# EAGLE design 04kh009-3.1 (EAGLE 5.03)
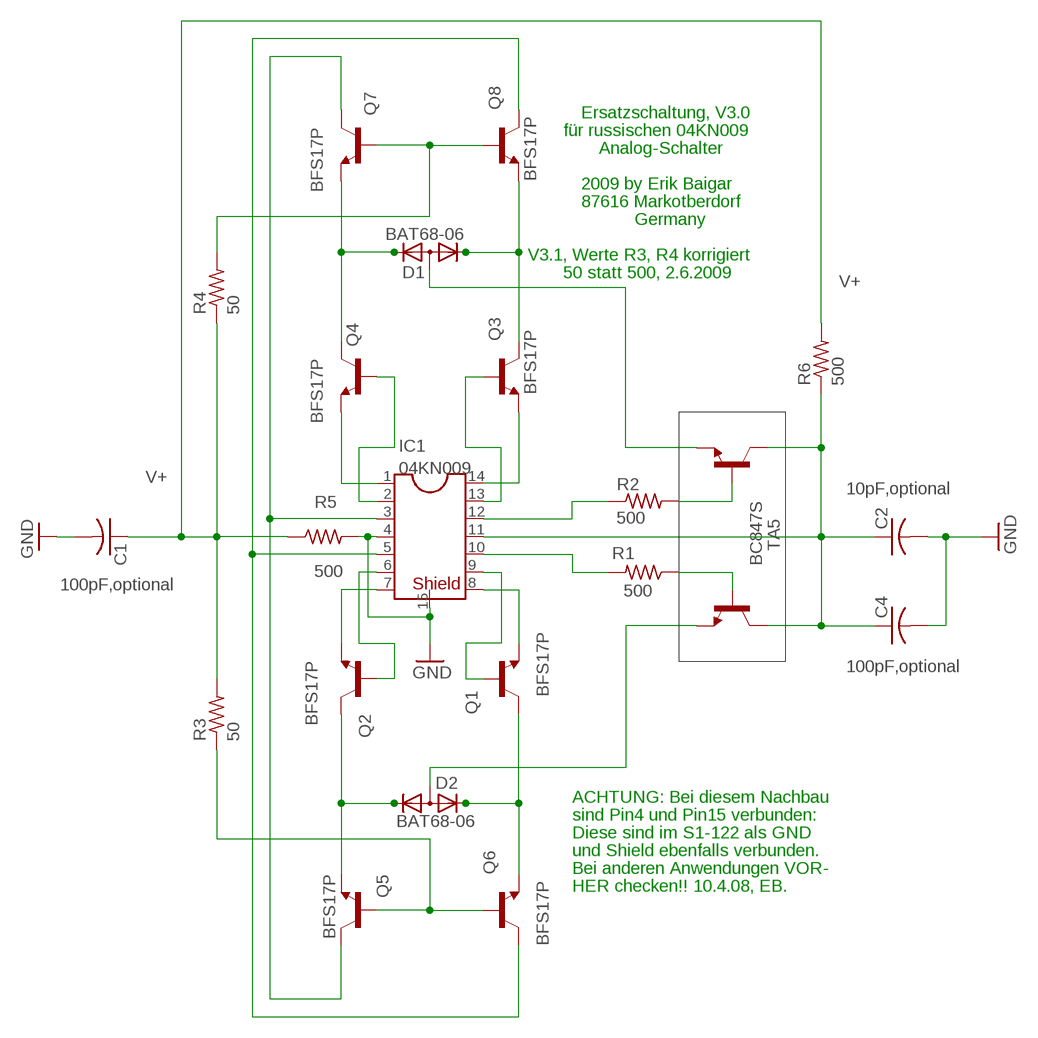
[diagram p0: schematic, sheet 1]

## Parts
C1  100pF,optional  C-USC0805  [C0805]
C2  10pF,optional  C-USC0805  [C0805]
C4  100pF,optional  C-USC0805  [C0805]
D1  BAT68-06  [SOT23]
D2  BAT68-06  [SOT23]
IC1  04KN009  04KH009  [04KH009]
Q1  BFS17P  BC847ASMD  [SOT23]
Q2  BFS17P  BC847ASMD  [SOT23]
Q3  BFS17P  BC847ASMD  [SOT23]
Q4  BFS17P  BC847ASMD  [SOT23]
Q5  BFS17P  BC847ASMD  [SOT23]
Q6  BFS17P  BC847ASMD  [SOT23]
Q7  BFS17P  BC847ASMD  [SOT23]
Q8  BFS17P  BC847ASMD  [SOT23]
R1  500  R-US_R0603  [R0603]
R2  500  R-US_R0603  [R0603]
R3  50  R-US_R0603  [R0603]
R4  50  R-US_R0603  [R0603]
R5  500  R-US_R0603  [R0603]
R6  500  R-US_R0603  [R0603]
TA5  BC847S  [SOT363]

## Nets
D1: D1.2(K2) Q4.3(C) Q7.2(E)
GND: C1.2 C2.2 C4.2 IC1.4 IC1.15 R5.2
N$1: IC1.1 Q4.2(E)
N$2: IC1.14 Q3.2(E)
N$3: IC1.2 Q4.1(B)
N$4: IC1.13 Q3.1(B)
N$5: IC1.7 Q2.2(E)
N$6: IC1.8 Q1.2(E)
N$7: IC1.6 Q2.1(B)
N$8: IC1.9 Q1.1(B)
N$10: D1.1(K1) Q3.3(C) Q8.2(E)
N$11: D1.3(A) TA5.1(E1)
N$12: D2.1(K1) Q2.3(C) Q5.2(E)
N$13: D2.2(K2) Q1.3(C) Q6.2(E)
N$14: D2.3(A) TA5.4(E2)
N$15: IC1.10 R1.2
N$16: IC1.12 R2.1
N$17: R2.2 TA5.2(B1)
N$18: R1.1 TA5.5(B2)
N$21: C2.1 C4.1 IC1.11 R6.1 TA5.3(C2) TA5.6(C1)
N$22: IC1.3 Q5.3(C) Q7.3(C)
N$23: IC1.5 Q6.3(C) Q8.3(C)
N$24: Q7.1(B) Q8.1(B) R4.2
N$25: Q5.1(B) Q6.1(B) R3.1
V+: C1.1 R3.2 R4.1 R5.1 R6.2

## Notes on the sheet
- Ersatzschaltung, V3.0
- für russischen 04KN009
- Analog-Schalter
- 2009 by Erik Baigar
- 87616 Markotberdorf
- Germany
- V3.1, Werte R3, R4 korrigiert
- 50 statt 500, 2.6.2009
- ACHTUNG: Bei diesem Nachbau
- sind Pin4 und Pin15 verbunden:
- Diese sind im S1-122 als GND
- und Shield ebenfalls verbunden.
- Bei anderen Anwendungen VOR-
- HER checken!! 10.4.08, EB.

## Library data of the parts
C1 C2 C4 = rcl:C-US: CAPACITOR, American symbol
D1 D2 = erik:BAT68-06
IC1 = erik:04KH009
Q1-Q8 = transistor-npn:BC847*: NPN Transistor
R1-R6 = rcl:R-US_: RESISTOR, American symbol
TA5 = sot363:BC847S

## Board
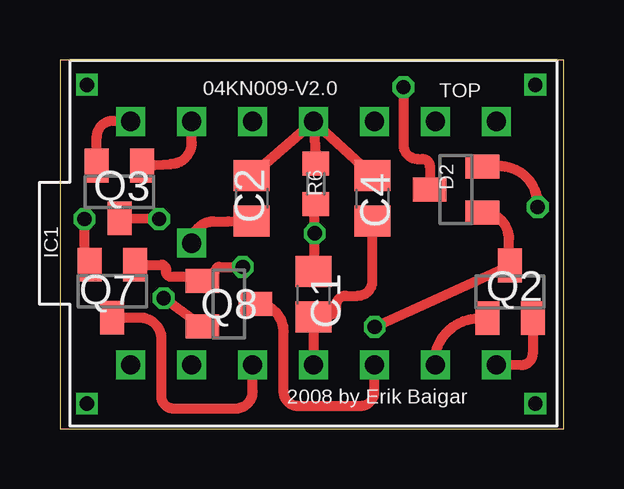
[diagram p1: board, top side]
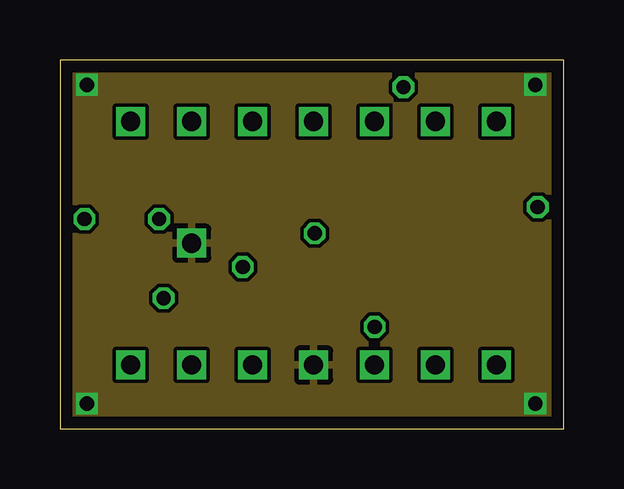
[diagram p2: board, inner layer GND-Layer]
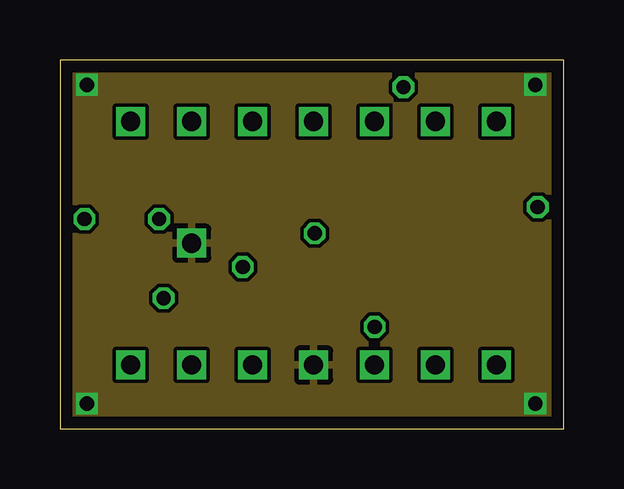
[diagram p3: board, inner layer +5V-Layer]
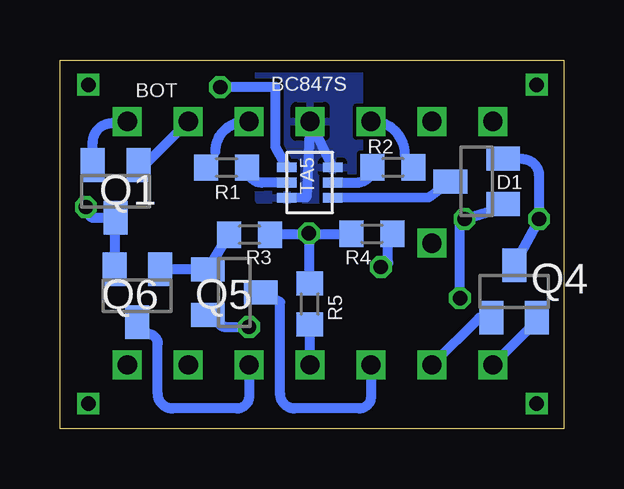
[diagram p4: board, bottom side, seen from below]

Size 21.01 x 15.39 mm. Coordinates in mm from the lower left corner, seen from the top.
Outline: 0,0 21.01,0 21.01,15.39 0,15.39 0,0
Copper layers (1*2*3*16): Top 0.035mm / dielectric 0.5mm / GND-Layer 0.035mm / dielectric 0.5mm / +5V-Layer 0.035mm / dielectric 0.5mm / Bottom 0.035mm
Design rules "leiton *": minimum track width 6mil, minimum drill 12mil, track to track 6mil, track to pad 6mil, pad to pad 6mil, via to via 6mil, smd to smd 6mil, copper to edge 20mil, drill to drill 8mil, minimum pad ring 8mil, minimum via ring 6mil, stop-mask expansion 3mil, vias tented up to drill 0mil, thermal gap 8mil

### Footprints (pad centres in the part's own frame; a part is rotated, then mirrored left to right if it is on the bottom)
C0805 = smd 1.3 x 1.5: 1 -0.95,0; 2 0.95,0
SOT23 = smd 1 x 1.4: 1 -0.95,-1.1; 2 0.95,-1.1; 3 0,1.1
04KH009 = drill 0.8 square: 1 -2.54,-5.08; 2 0,-5.08; 3 2.54,-5.08; 4 5.08,-5.08; 5 7.62,-5.08; 6 10.16,-5.08; 7 12.7,-5.08; 8 12.7,5.08; 9 10.16,5.08; 10 7.62,5.08; 11 5.08,5.08; 12 2.54,5.08; 13 0,5.08; 14 -2.54,5.08; 15 0,0
R0603 = smd 1 x 1.1: 1 -0.85,0; 2 0.85,0
SOT363 = smd 0.406 x 0.813: 1 0,0; 2 0.635,0; 3 1.27,0; 4 1.27,1.905; 5 0.635,1.905; 6 0,1.905

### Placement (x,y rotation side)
C1  10.57,5.61 270 top
C2  7.99,9.61 270 top
C4  13.03,9.61 270 top
D1  3.62,10.32 90 bottom
D2  16.51,9.98 90 top
IC1  5.49,7.74 0 top
Q1  18.68,9.9 180 bottom
Q2  18.76,5.71 0 top
Q3  2.48,9.88 180 top
Q4  2.06,5.73 0 bottom
Q5  13.73,5.69 270 bottom
Q6  17.78,5.55 180 bottom
Q7  2.18,5.74 180 top
Q8  7.04,5.21 270 top
R1  14.06,10.9 180 bottom
R2  7.12,10.91 180 bottom
R3  13.1,8.1 0 bottom
R4  7.99,8.13 0 bottom
R5  10.59,5.21 270 bottom
R6  10.67,10.22 270 top
TA5  9.64,9.64 90 bottom

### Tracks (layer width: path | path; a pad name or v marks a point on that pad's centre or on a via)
D1  (via drill 0.6 pad 0.61)
  Top 0.406: Q7.2 1.22,7.15 arc-90 1.02,7.35 v1.02,8.75
  Bottom 0.406: D1.2 1.72,11.25 arc90 1.02,10.55 v1.02,8.75 Q4.3
GND  (via drill 0.6)
  Top 0.406: IC1.4 C1.2 11.22,4.75 arc90 11.52,5.05 11.52,5.15 arc-90 11.92,5.55 12.42,5.55 arc90 13.02,6.15 C4.2 | IC1.15 arc-90 6.4,8.65 7.02,8.65 C2.2
  Bottom 0.406: R5.2 arc90 10.57,4.34 IC1.4
  other vias: 1.12,14.35 19.82,14.35 19.82,1.05 1.12,1.05
  pour GND-Layer: 0.42,14.95 20.42,14.95 20.42,0.45 0.52,0.45
  pour +5V-Layer: 0.62,14.85 20.42,14.85 20.42,0.55 0.62,0.55
N$1
  Bottom 0.254: Q4.2 1.51,4.1
  Bottom 0.406: 1.51,4.1 IC1.1
N$2
  Top 0.254: Q3.2 1.53,11.4
  Top 0.406: 1.53,11.4 1.53,12.16 arc-90 2.22,12.85 IC1.14
N$3
  Bottom 0.254: Q4.1 3.52,4.63
  Bottom 0.406: 3.52,4.63 IC1.2
N$4
  Top 0.254: Q3.1 3.65,10.98
  Top 0.406: 3.65,10.98 4.62,11.05 arc90 5.49,11.92 IC1.13
N$5
  Top 0.254: Q2.2 19.71,4.18
  Top 0.406: IC1.7 19.22,2.65 arc90 19.71,3.14 19.71,4.18
N$6
  Bottom 0.254: Q1.2 19.63,11.38
  Bottom 0.406: 19.63,11.38 19.63,11.94 arc90 18.82,12.75 IC1.8
N$7
  Top 0.254: 17.6,4.61 Q2.1
  Top 0.406: IC1.6 15.62,2.75 arc-90 17.48,4.61 17.6,4.61
  Bottom 0.254: IC1.6 arc90 15.72,2.73
N$8
  Bottom 0.254: Q1.1 17.47,11
  Bottom 0.406: 17.47,11 IC1.9
N$10  (via drill 0.6 pad 0.61)
  Top 0.406: Q8.2 v4.32,5.45 | v4.13,8.76 Q3.3
  Bottom 0.406: v4.32,5.45 4.32,8.55 arc-90 v4.13,8.75 v4.13,8.76 2.82,9.15 D1.1
N$11
  Bottom 0.406: D1.3 5.62,9.65 TA5.1
N$12  (via drill 0.6 pad 0.61)
  Top 0.406: D2.1 arc-90 18.72,7.92 18.72,6.95 Q2.3 v13.12,4.25
  Bottom 0.406: v13.12,4.25 14.12,4.25 arc90 14.42,4.55 Q5.2
N$13  (via drill 0.6 pad 0.61)
  Top 0.406: v19.92,9.25 arc90 18.42,10.95 17.62,10.95 D2.2
  Bottom 0.406: v19.92,9.25 19.82,9.05 arc-90 19.57,8.8 Q1.3 Q6.2
N$14  (via drill 0.6 pad 0.61)
  Top 0.406: v14.32,14.25 14.32,11.85 arc90 14.92,11.25 15.12,11.25 arc-90 15.42,10.95 D2.3
  Bottom 0.406: TA5.4 12.02,11.75 12.02,14.25 v14.32,14.25
N$15
  Bottom 0.254: 13.25,12.82 IC1.10 | R1.2 14.52,11.55
  Bottom 0.406: 14.52,11.55 arc90 13.25,12.82
N$16
  Bottom 0.254: R2.1 6.62,11.45 | 7.99,12.82 IC1.12
  Bottom 0.406: 6.62,11.45 arc-90 7.99,12.82
N$17
  Bottom 0.406: R2.2 arc90 8.61,10.27 TA5.2
N$18
  Bottom 0.406: R1.1 arc-90 12.59,10.27 TA5.5
N$21
  Top 0.254: 10.61,12.84 IC1.11
  Top 0.406: R6.1 IC1.11 C4.1 | C2.1 10.61,12.84
  Bottom 0.406: TA5.3 IC1.11 10.72,9.65 TA5.6
  pour Bottom: 8.52,9.55 12.72,9.55 12.72,14.85 8.52,14.85
N$22
  Top 0.406: Q7.3 3.33,4.64 arc-90 4.22,3.75 4.22,1.35 arc90 4.72,0.85 7.33,0.85 arc90 8.03,1.55 IC1.3
  Bottom 0.406: Q5.3 11.82,5.29 11.82,1.45 arc-90 11.22,0.85 8.52,0.85 arc-90 8.03,1.34 IC1.3
N$23
  Top 0.406: Q8.3 8.12,5.25 arc-90 9.32,4.05 9.32,1.55 arc90 9.92,0.95 12.51,0.95 arc90 13.11,1.55 IC1.5
  Bottom 0.254: 17.78,4.11 Q6.3
  Bottom 0.406: 17.78,4.11 17.32,3.95 arc90 16.92,3.55 16.92,1.45 arc-90 16.32,0.85 13.62,0.85 arc-90 13.11,1.36 IC1.5
N$24  (via drill 0.6 pad 0.61)
  Top 0.406: Q7.1 4.23,6.84 arc-90 4.42,6.65 4.42,6.55 arc90 4.62,6.35 5.72,6.35 Q8.1 6.52,6.65 arc-90 6.62,6.75 v7.62,6.75
  Bottom 0.406: v7.62,6.75 7.52,6.75 arc-90 7.32,6.95 7.32,7.95 arc90 R4.2
N$25
  Bottom 0.406: Q6.1 Q5.1 R3.1
V+  (via drill 0.6 pad 0.61)
  Top 0.406: R6.2 arc90 10.62,9.32 v10.62,8.15 10.62,6.61 arc-90 C1.1
  Bottom 0.254: v10.62,8.15 arc90 10.68,8.1
  Bottom 0.406: R4.1 10.6,8.13 arc90 v10.62,8.15 10.62,6.09 arc-90 R5.1 | 10.68,8.1 R3.2

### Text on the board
tPlace: TOP
bPlace: BOT
tNames: 04KN009-V2.0 | 2008 by Erik Baigar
